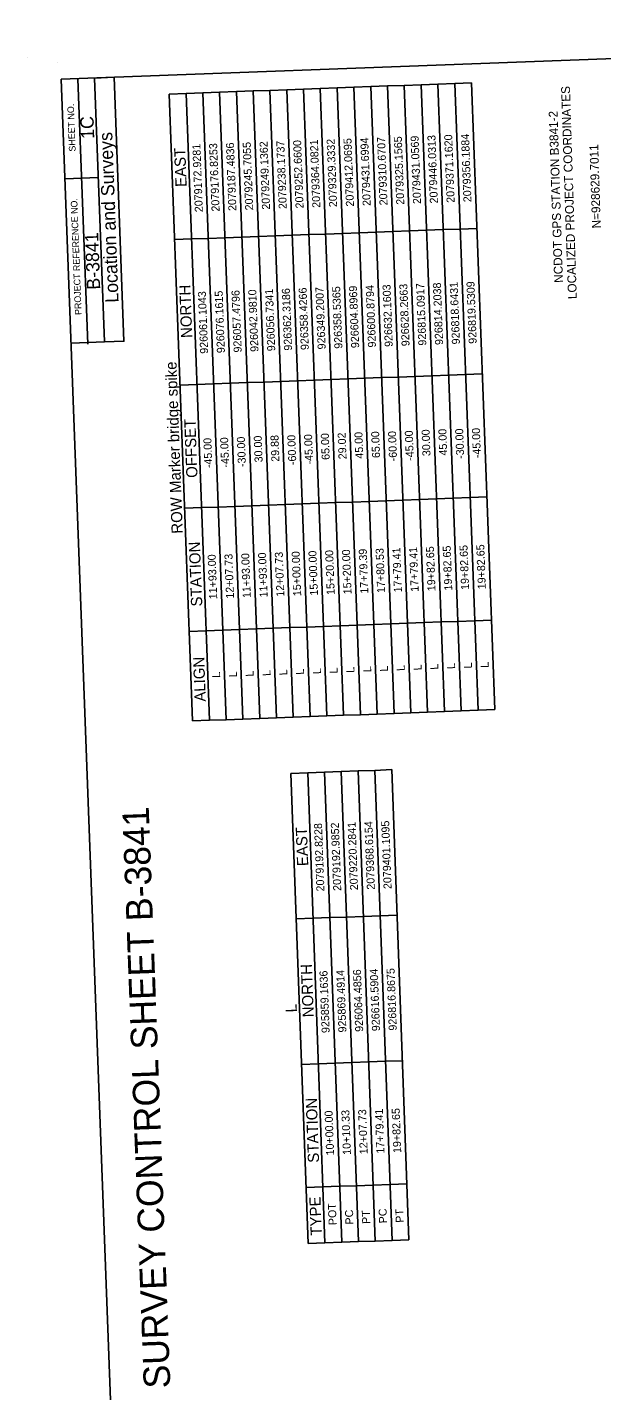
# Model space of a CAD drawing. Extents: x 2078190 to 2080463, y 924799 to 928082.
# Drawn here: x 2078190 to 2079036, y 926073 to 928082 of the extents above; entities that cross this region are included whole.
import ezdxf

# ---------------------------------------------------------------- set-up
doc = ezdxf.new("R2010")
doc.units = 0
for name, color, linetype in [('CTL GPS Horizontal Text', 7, 'Continuous'), ('CTL Sheet Border CELL', 7, 'Continuous'), ('CTL Sheet Notes CELL', 7, 'Continuous'), ('CTL Sheet Table Cell', 7, 'Continuous'), ('CTL Sheet Text', 7, 'Continuous')]:
    doc.layers.add(name, color=color, linetype=linetype)

msp = doc.modelspace()

# ---------------------------------------------------------------- linework, layer by layer
at = {"layer": 'CTL Sheet Border CELL'}
for p, q in [((2078189.8, 928037.2), (2078189.8, 928037.2)), ((2078234, 928030), (2078234, 928030)), ((2078234, 928030), (2078234, 928030)), ((2078279.1, 927615.5), (2078264.5, 928006.7)), ((2078245.5, 927859.1), (2078294.4, 927861)), ((2078254.5, 927616.9), (2078303.4, 927618.7))]:
    msp.add_line(p, q, dxfattribs=at)
for points in [[(2078239.9, 928005.8), (2078349.5, 925073), (2080402.4, 925149.7), (2080292.8, 928082.5)], [(2078303.4, 927618.7), (2078288.9, 928007.6), (2078317.7, 928008.7), (2078332.2, 927619.8)]]:
    msp.add_lwpolyline(points, close=True, dxfattribs=at)
at = {"layer": 'CTL Sheet Table Cell'}
for p, q in [((2078399.1, 927984), (2078423.8, 927984.9)), ((2078433.5, 927060.3), (2078399.1, 927984)), ((2078423.8, 927984.9), (2078448.6, 927985.8)), ((2078458.2, 927061.2), (2078423.8, 927984.9)), ((2078448.6, 927985.8), (2078473.3, 927986.7)), ((2078482.9, 927062.1), (2078448.6, 927985.8)), ((2078473.3, 927986.7), (2078498, 927987.7)), ((2078507.7, 927063.1), (2078473.3, 927986.7)), ((2078498, 927987.7), (2078522.8, 927988.6)), ((2078532.4, 927064), (2078498, 927987.7)), ((2078522.8, 927988.6), (2078547.5, 927989.5)), ((2078557.2, 927064.9), (2078522.8, 927988.6)), ((2078547.5, 927989.5), (2078572.3, 927990.4)), ((2078581.9, 927065.8), (2078547.5, 927989.5)), ((2078572.3, 927990.4), (2078597, 927991.3)), ((2078606.7, 927066.7), (2078572.3, 927990.4)), ((2078597, 927991.3), (2078621.7, 927992.3)), ((2078631.4, 927067.7), (2078597, 927991.3)), ((2078621.7, 927992.3), (2078646.5, 927993.2)), ((2078656.1, 927068.6), (2078621.7, 927992.3)), ((2078646.5, 927993.2), (2078671.2, 927994.1)), ((2078680.9, 927069.5), (2078646.5, 927993.2)), ((2078671.2, 927994.1), (2078696, 927995)), ((2078705.6, 927070.4), (2078671.2, 927994.1)), ((2078696, 927995), (2078720.7, 927996)), ((2078730.4, 927071.4), (2078696, 927995)), ((2078720.7, 927996), (2078745.4, 927996.9)), ((2078755.1, 927072.3), (2078720.7, 927996)), ((2078745.4, 927996.9), (2078770.2, 927997.8)), ((2078779.8, 927073.2), (2078745.4, 927996.9)), ((2078770.2, 927997.8), (2078794.9, 927998.7)), ((2078804.6, 927074.1), (2078770.2, 927997.8)), ((2078794.9, 927998.7), (2078819.7, 927999.6)), ((2078829.3, 927075), (2078794.9, 927998.7)), ((2078819.7, 927999.6), (2078844.4, 928000.6)), ((2078854.1, 927076), (2078819.7, 927999.6)), ((2078878.8, 927076.9), (2078844.4, 928000.6)), ((2078679.2, 927779.7), (2078704, 927780.6)), ((2078704, 927780.6), (2078728.7, 927781.5)), ((2078728.7, 927781.5), (2078753.4, 927782.4)), ((2078753.4, 927782.4), (2078778.2, 927783.4)), ((2078778.2, 927783.4), (2078802.9, 927784.3)), ((2078802.9, 927784.3), (2078827.7, 927785.2)), ((2078827.7, 927785.2), (2078852.4, 927786.1)), ((2078407.1, 927769.6), (2078431.8, 927770.5)), ((2078431.8, 927770.5), (2078456.5, 927771.4)), ((2078456.5, 927771.4), (2078481.3, 927772.3)), ((2078481.3, 927772.3), (2078506, 927773.2)), ((2078506, 927773.2), (2078530.8, 927774.2)), ((2078530.8, 927774.2), (2078555.5, 927775.1)), ((2078555.5, 927775.1), (2078580.2, 927776)), ((2078580.2, 927776), (2078605, 927776.9)), ((2078605, 927776.9), (2078629.7, 927777.8)), ((2078629.7, 927777.8), (2078654.5, 927778.8)), ((2078654.5, 927778.8), (2078679.2, 927779.7)), ((2078514, 927558.8), (2078538.7, 927559.7)), ((2078538.7, 927559.7), (2078563.5, 927560.7)), ((2078563.5, 927560.7), (2078588.2, 927561.6)), ((2078588.2, 927561.6), (2078613, 927562.5)), ((2078613, 927562.5), (2078637.7, 927563.4)), ((2078637.7, 927563.4), (2078662.5, 927564.3)), ((2078662.5, 927564.3), (2078687.2, 927565.3)), ((2078687.2, 927565.3), (2078711.9, 927566.2)), ((2078711.9, 927566.2), (2078736.7, 927567.1)), ((2078736.7, 927567.1), (2078761.4, 927568)), ((2078761.4, 927568), (2078786.2, 927568.9)), ((2078786.2, 927568.9), (2078810.9, 927569.9)), ((2078810.9, 927569.9), (2078835.6, 927570.8)), ((2078835.6, 927570.8), (2078860.4, 927571.7)), ((2078415, 927555.1), (2078439.8, 927556)), ((2078439.8, 927556), (2078464.5, 927557)), ((2078464.5, 927557), (2078489.3, 927557.9)), ((2078489.3, 927557.9), (2078514, 927558.8)), ((2078520.8, 927377.4), (2078545.5, 927378.3)), ((2078545.5, 927378.3), (2078570.2, 927379.2)), ((2078570.2, 927379.2), (2078595, 927380.1)), ((2078595, 927380.1), (2078619.7, 927381.1)), ((2078619.7, 927381.1), (2078644.5, 927382)), ((2078644.5, 927382), (2078669.2, 927382.9)), ((2078669.2, 927382.9), (2078694, 927383.8)), ((2078694, 927383.8), (2078718.7, 927384.7)), ((2078718.7, 927384.7), (2078743.4, 927385.7)), ((2078743.4, 927385.7), (2078768.2, 927386.6)), ((2078768.2, 927386.6), (2078792.9, 927387.5)), ((2078792.9, 927387.5), (2078817.7, 927388.4)), ((2078817.7, 927388.4), (2078842.4, 927389.4)), ((2078842.4, 927389.4), (2078867.1, 927390.3)), ((2078421.8, 927373.7), (2078446.5, 927374.6)), ((2078446.5, 927374.6), (2078471.3, 927375.5)), ((2078471.3, 927375.5), (2078496, 927376.5)), ((2078496, 927376.5), (2078520.8, 927377.4)), ((2078552.3, 927196.9), (2078577, 927197.8)), ((2078577, 927197.8), (2078601.7, 927198.7)), ((2078601.7, 927198.7), (2078626.5, 927199.6)), ((2078626.5, 927199.6), (2078651.2, 927200.5)), ((2078651.2, 927200.5), (2078676, 927201.5)), ((2078676, 927201.5), (2078700.7, 927202.4)), ((2078700.7, 927202.4), (2078725.4, 927203.3)), ((2078725.4, 927203.3), (2078750.2, 927204.2)), ((2078750.2, 927204.2), (2078774.9, 927205.2)), ((2078774.9, 927205.2), (2078799.7, 927206.1)), ((2078799.7, 927206.1), (2078824.4, 927207)), ((2078824.4, 927207), (2078849.2, 927207.9)), ((2078849.2, 927207.9), (2078873.9, 927208.8)), ((2078428.6, 927192.3), (2078453.3, 927193.2)), ((2078453.3, 927193.2), (2078478, 927194.1)), ((2078478, 927194.1), (2078502.8, 927195)), ((2078502.8, 927195), (2078527.5, 927195.9)), ((2078527.5, 927195.9), (2078552.3, 927196.9)), ((2078854.1, 927076), (2078878.8, 927076.9)), ((2078433.5, 927060.3), (2078458.2, 927061.2)), ((2078458.2, 927061.2), (2078482.9, 927062.1)), ((2078482.9, 927062.1), (2078507.7, 927063.1)), ((2078507.7, 927063.1), (2078532.4, 927064)), ((2078532.4, 927064), (2078557.2, 927064.9)), ((2078557.2, 927064.9), (2078581.9, 927065.8)), ((2078581.9, 927065.8), (2078606.7, 927066.7)), ((2078606.7, 927066.7), (2078631.4, 927067.7)), ((2078631.4, 927067.7), (2078656.1, 927068.6)), ((2078656.1, 927068.6), (2078680.9, 927069.5)), ((2078680.9, 927069.5), (2078705.6, 927070.4)), ((2078705.6, 927070.4), (2078730.4, 927071.4)), ((2078730.4, 927071.4), (2078755.1, 927072.3)), ((2078755.1, 927072.3), (2078779.8, 927073.2)), ((2078779.8, 927073.2), (2078804.6, 927074.1)), ((2078804.6, 927074.1), (2078829.3, 927075)), ((2078829.3, 927075), (2078854.1, 927076)), ((2078578.4, 926983), (2078603.1, 926983.9)), ((2078603.8, 926290.2), (2078578.4, 926983)), ((2078603.1, 926983.9), (2078627.9, 926984.8)), ((2078628.5, 926291.2), (2078603.1, 926983.9)), ((2078627.9, 926984.8), (2078652.6, 926985.7)), ((2078653.2, 926292.1), (2078627.9, 926984.8)), ((2078652.6, 926985.7), (2078677.4, 926986.6)), ((2078678, 926293), (2078652.6, 926985.7)), ((2078677.4, 926986.6), (2078702.1, 926987.5)), ((2078702.7, 926293.9), (2078677.4, 926986.6)), ((2078702.1, 926987.5), (2078726.9, 926988.5)), ((2078727.5, 926294.8), (2078702.1, 926987.5)), ((2078752.2, 926295.7), (2078726.9, 926988.5)), ((2078586.3, 926768.6), (2078611, 926769.5)), ((2078611, 926769.5), (2078635.7, 926770.4)), ((2078635.7, 926770.4), (2078660.5, 926771.3)), ((2078660.5, 926771.3), (2078685.2, 926772.2)), ((2078685.2, 926772.2), (2078710, 926773.1)), ((2078710, 926773.1), (2078734.7, 926774)), ((2078594.1, 926554.2), (2078618.8, 926555.1)), ((2078618.8, 926555.1), (2078643.6, 926556)), ((2078643.6, 926556), (2078668.3, 926556.9)), ((2078668.3, 926556.9), (2078693.1, 926557.8)), ((2078693.1, 926557.8), (2078717.8, 926558.7)), ((2078717.8, 926558.7), (2078742.6, 926559.6)), ((2078625.5, 926373.6), (2078650.2, 926374.5)), ((2078650.2, 926374.5), (2078675, 926375.4)), ((2078675, 926375.4), (2078699.7, 926376.3)), ((2078699.7, 926376.3), (2078724.5, 926377.3)), ((2078724.5, 926377.3), (2078749.2, 926378.2)), ((2078600.7, 926372.7), (2078625.5, 926373.6)), ((2078678, 926293), (2078702.7, 926293.9)), ((2078702.7, 926293.9), (2078727.5, 926294.8)), ((2078727.5, 926294.8), (2078752.2, 926295.7)), ((2078603.8, 926290.2), (2078628.5, 926291.2)), ((2078628.5, 926291.2), (2078653.2, 926292.1)), ((2078653.2, 926292.1), (2078678, 926293))]:
    msp.add_line(p, q, dxfattribs=at)

# ---------------------------------------------------------------- texts
at = {"layer": 'CTL GPS Horizontal Text'}
for s, p in [('LOCALIZED PROJECT COORDINATES', (2078999.7, 927682.1)), ('NCDOT GPS STATION B3841-2', (2078979.4, 927706.1)), ('N=928629.7011', (2079035.2, 927786.3))]:
    msp.add_text(s, height=12.969, rotation=91.861, dxfattribs=at).set_placement(p)
at = {"layer": 'CTL Sheet Border CELL'}
for s, height, p in [('SHEET NO.', 9.78, (2078261.1, 927899.5)), ('1C', 19.57, (2078288.6, 927918.4)), ('Location and Surveys', 19.566, (2078324.4, 927676.9)), ('PROJECT REFERENCE NO.', 9.783, (2078269.9, 927658.7)), ('B-3841', 19.57, (2078297.4, 927696.1)), ('SURVEY CONTROL SHEET B-3841', 39.13, (2078400.8, 926077.4))]:
    msp.add_text(s, height=height, rotation=92.1397, dxfattribs=at).set_placement(p)
at = {"layer": 'CTL Sheet Notes CELL'}
for s, height, rotation, p in [('EAST', 16.51, 92.1326, (2078424.8, 927847.5)), ('NORTH', 16.51, 92.1326, (2078433.1, 927624.9)), ('ROW Marker bridge spike', 16.506, 92.1326, (2078419.1, 927336.5)), ('OFFSET', 16.51, 92.1326, (2078440.8, 927418.8)), ('STATION', 16.51, 92.1326, (2078447.8, 927229.2)), ('ALIGN', 16.51, 92.1326, (2078453, 927088.9)), ('EAST', 16.51, 92.0969, (2078604, 926846.6)), ('NORTH', 16.51, 92.0969, (2078612.2, 926623.9)), ('L', 16.5, 92.0969, (2078587.2, 926631)), ('STATION', 16.51, 92.0969, (2078620, 926409.6)), ('TYPE', 16.51, 92.0969, (2078624, 926302.2))]:
    msp.add_text(s, height=height, rotation=rotation, dxfattribs=at).set_placement(p)
at = {"layer": 'CTL Sheet Text'}
for s, height, rotation, p in [('2079325.1565', 11.79, 92.1326, (2078745.5, 927821.2)), ('2079431.0569', 11.79, 92.1326, (2078770.2, 927822.2)), ('2079446.0313', 11.79, 92.1326, (2078795, 927823.1)), ('2079371.1620', 11.79, 92.1326, (2078819.7, 927824)), ('2079356.1884', 11.79, 92.1326, (2078844.5, 927824.9)), ('2079172.9281', 11.79, 92.1326, (2078448.6, 927810.2)), ('2079176.8253', 11.79, 92.1326, (2078473.3, 927811.1)), ('2079187.4836', 11.79, 92.1326, (2078498.1, 927812)), ('2079245.7055', 11.79, 92.1326, (2078522.8, 927812.9)), ('2079249.1362', 11.79, 92.1326, (2078547.6, 927813.9)), ('2079238.1737', 11.79, 92.1326, (2078572.3, 927814.8)), ('2079252.6600', 11.79, 92.1326, (2078597.1, 927815.7)), ('2079364.0821', 11.79, 92.1326, (2078621.8, 927816.6)), ('2079329.3332', 11.79, 92.1326, (2078646.5, 927817.6)), ('2079412.0695', 11.79, 92.1326, (2078671.3, 927818.5)), ('2079431.6994', 11.79, 92.1326, (2078696, 927819.4)), ('2079310.6707', 11.79, 92.1326, (2078720.8, 927820.3)), ('926358.5365', 11.79, 92.1326, (2078654.3, 927609)), ('926604.8969', 11.79, 92.1326, (2078679, 927609.9)), ('926600.8794', 11.79, 92.1326, (2078703.8, 927610.8)), ('926632.1603', 11.79, 92.1326, (2078728.5, 927611.7)), ('926628.2663', 11.79, 92.1326, (2078753.3, 927612.7)), ('926815.0917', 11.79, 92.1326, (2078778, 927613.6)), ('926814.2038', 11.79, 92.1326, (2078802.7, 927614.5)), ('926818.6431', 11.79, 92.1326, (2078827.5, 927615.4)), ('926819.5309', 11.79, 92.1326, (2078852.2, 927616.3)), ('926061.1043', 11.79, 92.1326, (2078456.4, 927601.6)), ('926076.1615', 11.79, 92.1326, (2078481.1, 927602.5)), ('926057.4796', 11.79, 92.1326, (2078505.9, 927603.4)), ('926042.9810', 11.79, 92.1326, (2078530.6, 927604.4)), ('926056.7341', 11.79, 92.1326, (2078555.3, 927605.3)), ('926362.3186', 11.79, 92.1326, (2078580.1, 927606.2)), ('926358.4266', 11.79, 92.1326, (2078604.8, 927607.1)), ('926349.2007', 11.79, 92.1326, (2078629.6, 927608)), ('30.00', 11.79, 92.1326, (2078536.7, 927441.5)), ('29.88', 11.79, 92.1326, (2078561.4, 927442.4)), ('-60.00', 11.79, 92.1326, (2078586.4, 927437.5)), ('-45.00', 11.79, 92.1326, (2078611.1, 927438.4)), ('65.00', 11.79, 92.1326, (2078635.6, 927445.2)), ('29.02', 11.79, 92.1326, (2078660.4, 927446.1)), ('45.00', 11.79, 92.1326, (2078685.1, 927447)), ('65.00', 11.79, 92.1326, (2078709.8, 927447.9)), ('-60.00', 11.79, 92.1326, (2078734.8, 927443)), ('-45.00', 11.79, 92.1326, (2078759.5, 927443.9)), ('30.00', 11.79, 92.1326, (2078784.1, 927450.7)), ('45.00', 11.79, 92.1326, (2078808.8, 927451.6)), ('-30.00', 11.79, 92.1326, (2078833.8, 927446.7)), ('-45.00', 11.79, 92.1326, (2078858.5, 927447.6)), ('-45.00', 11.79, 92.1326, (2078462.7, 927432.9)), ('-45.00', 11.79, 92.1326, (2078487.4, 927433.8)), ('-30.00', 11.79, 92.1326, (2078512.1, 927434.7)), ('19+82.65', 11.79, 92.1326, (2078816.2, 927252.7)), ('19+82.65', 11.79, 92.1326, (2078841, 927253.6)), ('19+82.65', 11.79, 92.1326, (2078865.7, 927254.5)), ('11+93.00', 11.79, 92.1326, (2078469.8, 927239.8)), ('12+07.73', 11.79, 92.1326, (2078494.6, 927240.7)), ('11+93.00', 11.79, 92.1326, (2078519.3, 927241.6)), ('11+93.00', 11.79, 92.1326, (2078544.1, 927242.5)), ('12+07.73', 11.79, 92.1326, (2078568.8, 927243.5)), ('15+00.00', 11.79, 92.1326, (2078593.6, 927244.4)), ('15+00.00', 11.79, 92.1326, (2078618.3, 927245.3)), ('15+20.00', 11.79, 92.1326, (2078643, 927246.2)), ('15+20.00', 11.79, 92.1326, (2078667.8, 927247.1)), ('17+79.39', 11.79, 92.1326, (2078692.5, 927248.1)), ('17+80.53', 11.79, 92.1326, (2078717.3, 927249)), ('17+79.41', 11.79, 92.1326, (2078742, 927249.9)), ('17+79.41', 11.79, 92.1326, (2078766.7, 927250.8)), ('19+82.65', 11.79, 92.1326, (2078791.5, 927251.7)), ('L', 11.8, 92.1326, (2078622.6, 927129.5)), ('L', 11.8, 92.1326, (2078647.3, 927130.4)), ('L', 11.8, 92.1326, (2078672.1, 927131.4)), ('L', 11.8, 92.1326, (2078696.8, 927132.3)), ('L', 11.8, 92.1326, (2078721.6, 927133.2)), ('L', 11.8, 92.1326, (2078746.3, 927134.1)), ('L', 11.8, 92.1326, (2078771.1, 927135)), ('L', 11.8, 92.1326, (2078795.8, 927136)), ('L', 11.8, 92.1326, (2078820.5, 927136.9)), ('L', 11.8, 92.1326, (2078845.3, 927137.8)), ('L', 11.8, 92.1326, (2078870, 927138.7)), ('L', 11.8, 92.1326, (2078474.2, 927124)), ('L', 11.8, 92.1326, (2078498.9, 927124.9)), ('L', 11.8, 92.1326, (2078523.6, 927125.8)), ('L', 11.8, 92.1326, (2078548.4, 927126.7)), ('L', 11.8, 92.1326, (2078573.1, 927127.7)), ('L', 11.8, 92.1326, (2078597.9, 927128.6)), ('2079192.8228', 11.79, 92.0969, (2078627.8, 926809.2)), ('2079192.9852', 11.79, 92.0969, (2078652.6, 926810.1)), ('2079220.2841', 11.79, 92.0969, (2078677.3, 926811)), ('2079368.6154', 11.79, 92.0969, (2078702.1, 926811.9)), ('2079401.1095', 11.79, 92.0969, (2078726.8, 926812.8)), ('926816.8675', 11.79, 92.0969, (2078734.4, 926604.2)), ('925859.1636', 11.79, 92.0969, (2078635.5, 926600.6)), ('925869.4914', 11.79, 92.0969, (2078660.2, 926601.5)), ('926064.4856', 11.79, 92.0969, (2078684.9, 926602.4)), ('926616.5904', 11.79, 92.0969, (2078709.7, 926603.3)), ('10+00.00', 11.79, 92.0969, (2078642.1, 926420.2)), ('10+10.33', 11.79, 92.0969, (2078666.8, 926421.1)), ('12+07.73', 11.79, 92.0969, (2078691.6, 926422)), ('17+79.41', 11.79, 92.0969, (2078716.3, 926422.9)), ('19+82.65', 11.79, 92.0969, (2078741, 926423.8)), ('POT', 11.79, 92.0969, (2078645.8, 926317.5)), ('PC ', 11.79, 92.0969, (2078670.6, 926318.4)), ('PT ', 11.79, 92.0969, (2078695.3, 926319.3)), ('PC ', 11.79, 92.0969, (2078720.1, 926320.2)), ('PT ', 11.79, 92.0969, (2078744.8, 926321.1))]:
    msp.add_text(s, height=height, rotation=rotation, dxfattribs=at).set_placement(p)

doc.saveas('drawing.dxf')
